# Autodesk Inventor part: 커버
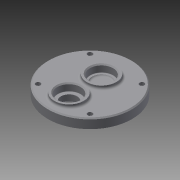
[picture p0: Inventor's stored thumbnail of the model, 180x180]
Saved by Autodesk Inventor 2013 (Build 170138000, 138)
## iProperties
Created: 2015-07
Part Number: 커버
Material: 일반
Document SubType Name: Modeling
Designer: user
Density: 1 g/cm^3
Author: user
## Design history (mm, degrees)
sketch "스케치1"
  geometry: C1 r 40 at (0, 0); 1 further point
  constraints: 1 centre point, 1 coincident
  dimensions: "d0" = 80 diameter of C1
extrude "돌출1" new body sketch "스케치1" distance "d1" = 9; taper "d2" = 0 deg
sketch "스케치2"
  geometry: L1 (0, 0)-(0, 11); C1 r 40 at (0, 0) reference; C2 r 14 at (0, 11)
  constraints: 2 end point, 1 centre point, 1 coincident, 1 vertical
  dimensions: "d3" = 11 distance of L1.start L1.end; "d4" = 28 diameter of C2
extrude "돌출2" join sketch "스케치2" distance "d5" = 3; taper "d6" = 0 deg
sketch "스케치3" dims "d44" = 1
  geometry: L1 (0, 0)-(0, -20); C1 r 40 at (0, 0) reference; C2 r 14 at (0, -20)
  constraints: 2 end point, 1 centre point, 1 coincident, 1 vertical
  dimensions: "d7" = 20 distance of L1.start L1.end; "d8" = 28 diameter of C2
extrude "돌출3" join sketch "스케치3" distance "d9" = 3; taper "d10" = 0 deg
sketch "스케치4"
  geometry: L1 (0, 0)-(0, -20); C1 r 40 at (0, 0) reference; C2 r 15 at (0, -20)
  constraints: 2 end point, 1 centre point, 1 coincident, 1 vertical
  dimensions: "d11" = 20 distance of L1.start L1.end; "d12" = 30 diameter of C2
extrude "돌출4" join sketch "스케치4" distance "d13" = 4; taper "d14" = 0 deg
hole "구멍1" diameter "d17" = 15; stored, may be unused: countersink angle "d21" = 90 deg, drill point angle "d23" = 118 deg; dims "d15" = 10, "d16" = 10, "d18" = 6, "d19" = 22, "d20" = 7, "d22" = 8
hole "구멍2" diameter "d26" = 22; stored, may be unused: countersink angle "d30" = 90 deg, drill point angle "d32" = 118 deg; dims "d24" = 10, "d25" = 10, "d27" = 6, "d28" = 22, "d29" = 7, "d31" = 7
hole "구멍3" diameter "d35" = 18; stored, may be unused: countersink angle "d39" = 90 deg, drill point angle "d41" = 0 deg; dims "d33" = 10, "d34" = 10, "d36" = 6, "d37" = 22, "d38" = 7, "d40" = 8
fillet "모깎기1" dims "d42" = 2
fillet "모깎기2" dims "d43" = 0.3
chamfer "모따기1" distance "d44" = 1; stored, may be unused: second distance "d45" = 2, angle "d46" = 45 deg
fillet "모깎기3" dims "d47" = 0.3
fillet "모깎기4" dims "d48" = 2
sketch "스케치6"
  geometry: L1 (0, 0)-(24.749, 24.749); L2 (0, 0)-(35, 0); C1 r 40 at (0, 0) reference
  constraints: 4 end point, 1 equal length, 1 horizontal
  dimensions: "d51" = 35 distance of L1.start L1.end; "d52" = 45 deg angle of L2 L1
hole "구멍4" sketch "스케치6" at (24.749, 24.749) diameter "d53" = 4.5; stored, may be unused: countersink angle "d57" = 90 deg, drill point angle "d59" = 0 deg; dims "d54" = 6, "d55" = 8, "d56" = 4.4, "d58" = 8
chamfer "모따기2" distance "d64" = 1; stored, may be unused: second distance "d65" = 2, angle "d66" = 45 deg
node "솔리드1"
pattern_circular "원형 패턴1" dims angle "d61" = 360 deg
